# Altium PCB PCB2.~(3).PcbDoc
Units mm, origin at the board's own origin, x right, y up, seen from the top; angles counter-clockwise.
Board outline 101.6 x 109.09 mm, 2 copper layers (Top Layer, Bottom Layer); 25 components, 22 nets, 119 pads, 0 vias.
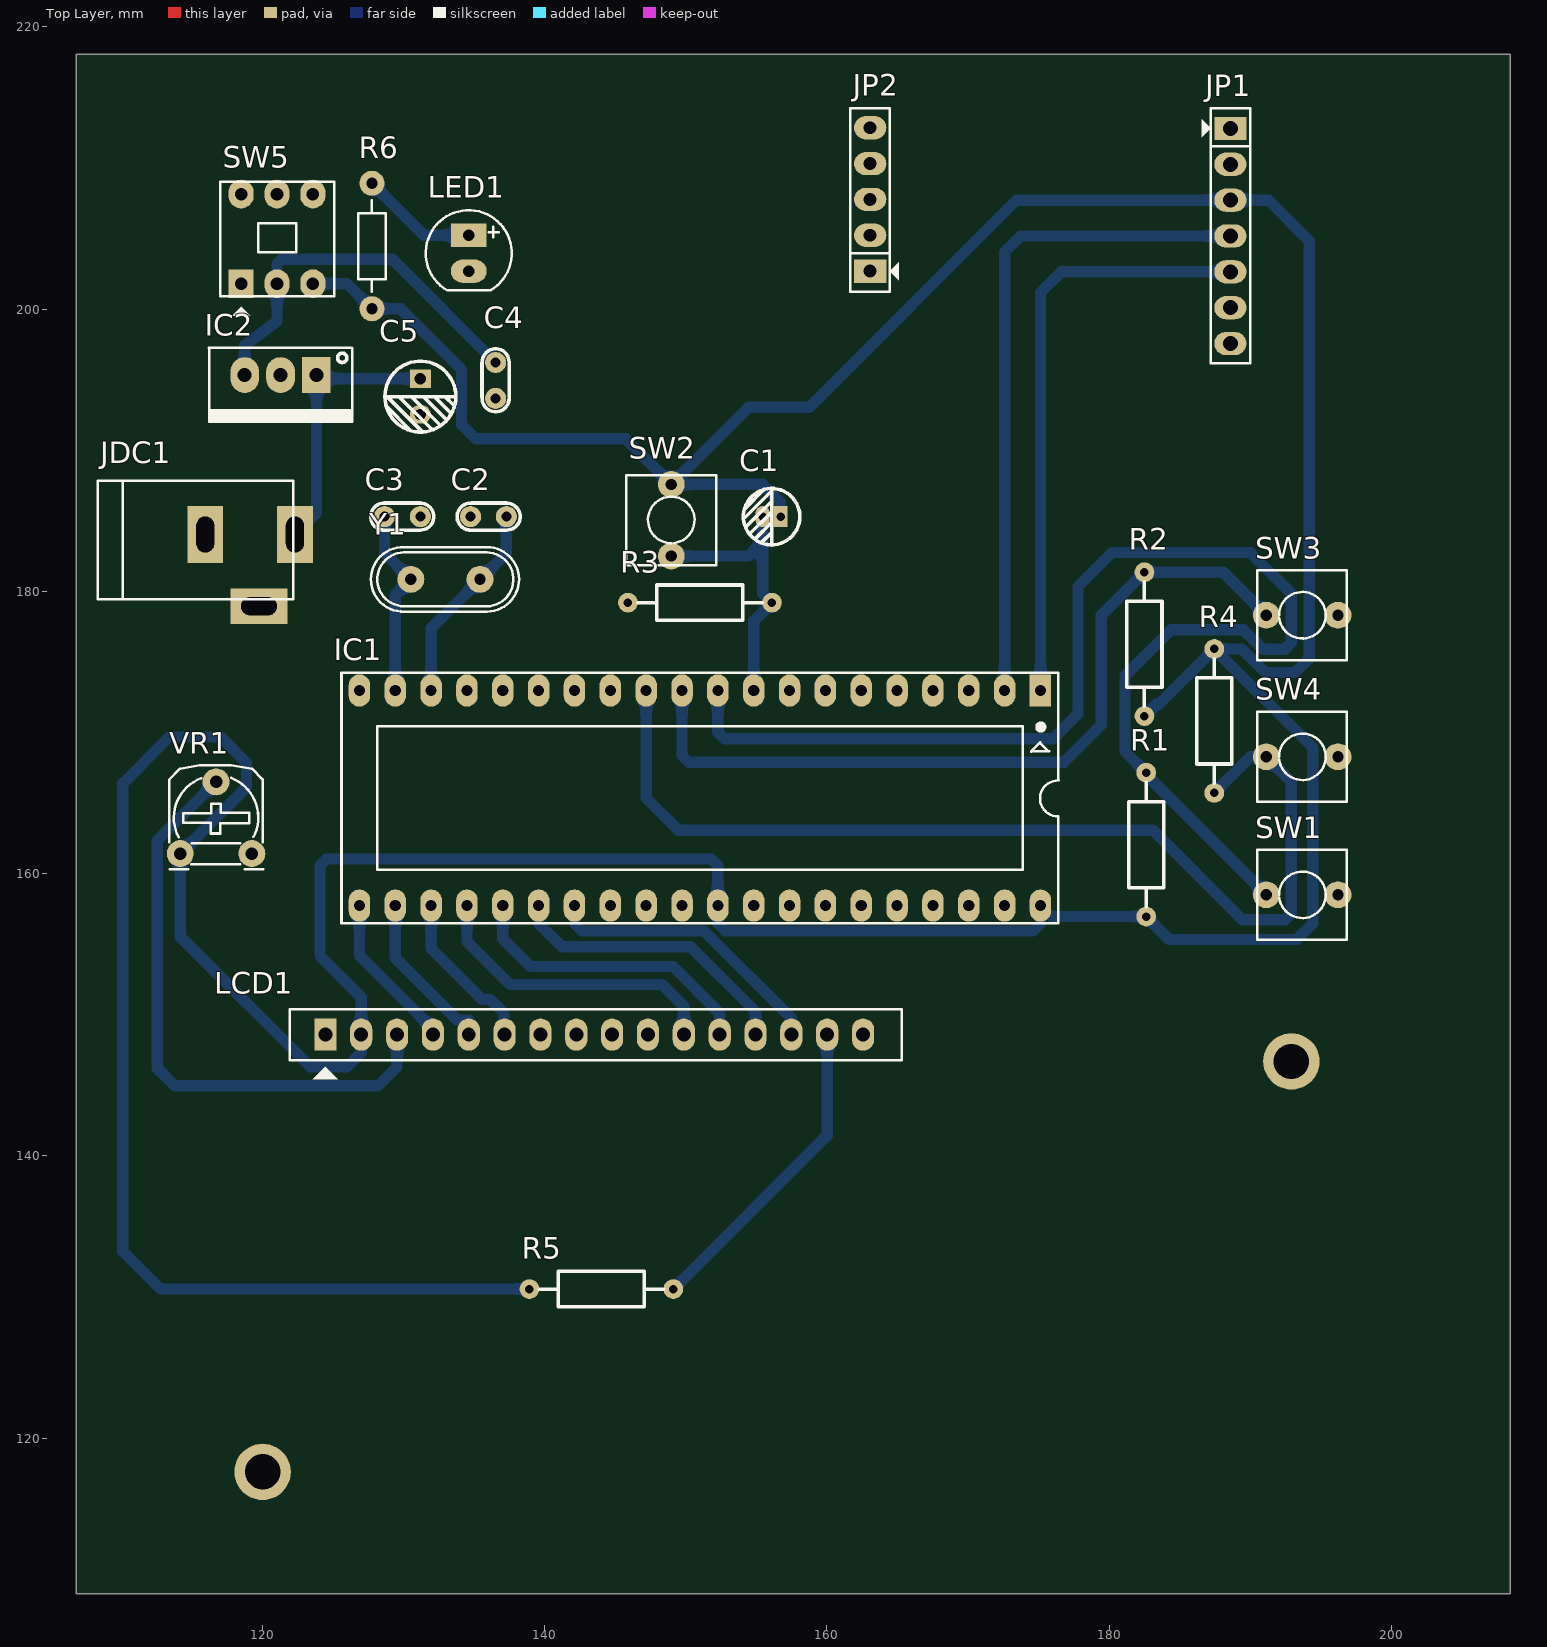
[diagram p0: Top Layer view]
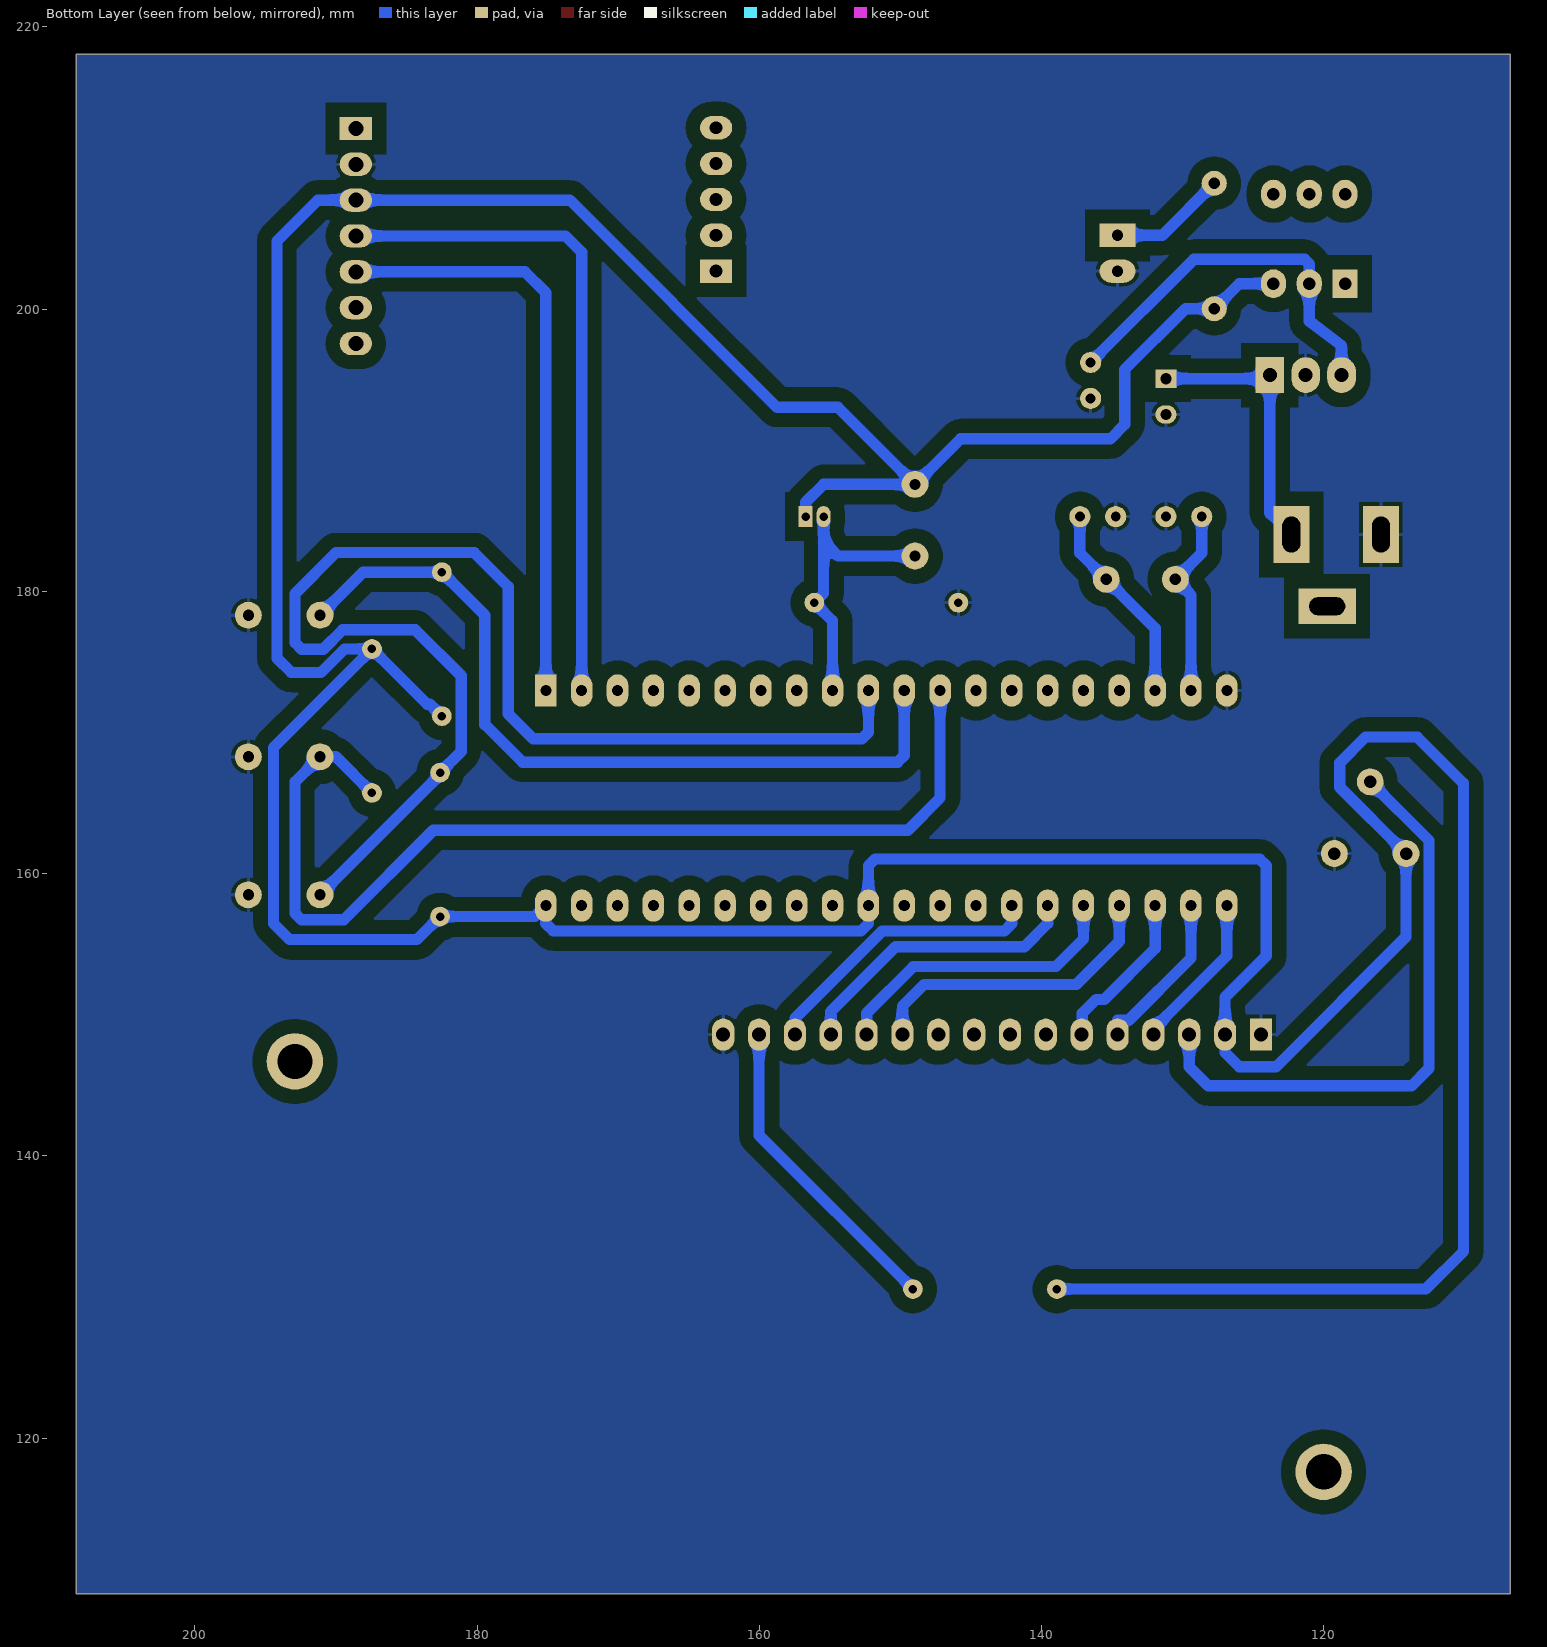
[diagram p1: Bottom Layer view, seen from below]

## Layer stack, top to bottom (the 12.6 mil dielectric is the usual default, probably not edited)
Top Solder: solder mask 0.0102, Solder Resist, Dk 3.5
Top Layer: signal copper 0.0356
Dielectric 1: dielectric 0.32, FR-4, Dk 4.8
Bottom Layer: signal copper 0.0356
Bottom Solder: solder mask 0.0102, Solder Resist, Dk 3.5

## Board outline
106.807,218.059 106.807,108.966 208.407,108.966 208.407,218.059

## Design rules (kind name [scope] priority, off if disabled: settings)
Clearance [All] p1: gap=0.2 ignorepadtopadclearanceinfootprint=FALSE
PolygonConnect [All] p1: connectstyle=Relief reliefconductorwidth=0.254 reliefentries=4 polygonreliefangle="90 Angle" airgapwidth=0.254
RoutingLayers [All] p1: top layer_v5=FALSE bottom layer_v5=TRUE
RoutingVias [All] p1: holewidth=0.711 width=1.27 viastyle="Through Hole" minholewidth=0.711 minwidth=1.27 maxholewidth=0.711 maxwidth=1.27
SolderMaskExpansion [All] p1: expansion=0.102 istentingtop=FALSE
Width [All] p1: maxlimit=0.8 minlimit=0.254 preferedwidth=0.8
29 further rules are at their usual default settings.

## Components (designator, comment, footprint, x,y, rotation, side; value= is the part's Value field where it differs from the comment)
C1 "10uF" "tu hoa 4mm" 156.083,185.293 r180 top
C2 "30pF" "tu gom" 136.017,185.293 r180 top
C3 "30pF" "tu gom" 129.921,185.293 r0 top
C4 "104" "tu gom" 136.525,194.945 r270 top
C5 "22uF" "tu hoa 5mm" 131.191,193.802 r270 top
IC1 "AT89S52" DIP40/W0.6 175.133,172.974 r180 top
IC2 "LM7805" QTO-220 123.825,195.326 r180 top
JDC1 "Jack DC" DC-IN 119.126,181.483 r0 top value="Jac DC"
JP1 "JP7 PIN" JP7_1 188.595,212.801 r270 top value=JP7
JP2 "JP5 PIN" JP5_1 163.068,202.692 r90 top value=JP5
LCD1 "LCD1602 XL" "LCD1602 with Jump" 124.46,148.59 r0 top
LED1 "LED" LED-5-RED 134.62,205.232 r270 top value="LED 3 ly Single Colour"
R1 "10K" "tro vach 1/4w" 182.626,162.052 r90 top
R2 "10K" "tro vach 1/4w" 182.499,176.256 r90 top
R3 "10k" "tro vach 1/4w" 151.003,179.197 r0 top
R4 "10K" "tro vach 1/4w" 187.452,170.815 r270 top
R5 "220R" "tro vach 1/4w" 144.018,130.556 r0 top
R6 "1k" R1/4W 127.762,208.915 r270 top value="R1/4W - 1K"
SW1 "SW" SW2 196.215,158.496 r180 top value="SW chip 2 pin"
SW2 "SW" SW2 148.971,187.579 r270 top value="SW chip 2 pin"
SW3 "SW" SW2 196.215,178.308 r180 top value="SW chip 2 pin"
SW4 "SW" SW2 196.215,168.275 r180 top value="SW chip 2 pin"
SW5 "SW6A" SW6 118.491,201.803 r90 top value=SW6
VR1 "1K" "Bien Tro Tam Giac Dung" 114.173,161.417 r0 top
Y1 "11Mhz" "Thach Anh 2 chan cam" 132.969,180.848 r0 top value=4Mhz

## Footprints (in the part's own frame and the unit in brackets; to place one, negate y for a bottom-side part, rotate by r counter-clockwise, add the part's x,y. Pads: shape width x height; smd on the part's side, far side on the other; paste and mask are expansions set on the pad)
"Bien Tro Tam Giac Dung" [mil] "RM065"
  round 75 hole 35: 1(0,0) 2(100,200) 3(200,0)
  silkscreen extent -31,-44 231,246, body extent -28,-50 228,228, height 279
DC-IN [mil] "Jac DC input"
  rect 100x160 hole 50 slot 100 at 90 deg: 1(125,100) 2(-125,100)
  rect 160x100 hole 50 slot 100 at 0 deg: 3(25,-100)
  silkscreen extent -425,-80 120,250, body extent -410,-105 134,269, height 434
DIP40/W0.6 [mil] "40 PIN, W 600mil, Pin to pin 100mil"
  rect 60x90 hole 31: 1(0,0)
  oval 60x90 hole 31: 2(100,0) 3(200,0) 4(300,0) 5(400,0) 6(500,0) 7(600,0) 8(700,0) 9(800,0) 10(900,0) 11(1000,0) 12(1100,0) 13(1200,0) 14(1300,0) 15(1400,0) 16(1500,0) 17(1600,0) 18(1700,0) 19(1800,0) 20(1900,0) 21(1900,600) 22(1800,600) 23(1700,600) 24(1600,600) 25(1500,600) 26(1400,600) 27(1300,600) 28(1200,600) 29(1100,600) 30(1000,600) 31(900,600) 32(800,600) 33(700,600) 34(600,600) 35(500,600) 36(400,600) 37(300,600) 38(200,600) 39(100,600) 40(0,600)
  silkscreen extent -50,-50 1950,650, body extent -82,-10 1982,600, height 224
JP5_1 [mil] "JP5"
  rect 65x90 hole 36: 1(0,0)
  oval 65x90 hole 36: 2(100,0) 3(200,0) 4(300,0) 5(400,0)
  silkscreen extent -57,-80 455,55, body extent -55,-48 455,50, height 366
JP7_1 [mil] "JP7"
  rect 65x90 hole 42: 1(0,0)
  oval 65x90 hole 42: 2(100,0) 3(200,0) 4(300,0) 5(400,0) 6(500,0) 7(600,0)
  silkscreen extent -57,-80 655,55, body extent -53,-47 657,51, height 366
"LCD1602 with Jump" [mil] "LCD dipslay 16x2, 16 pin"
  rect 62x90 hole 39: 1(0,0)
  oval 62x90 hole 39: 2(100,0) 3(200,0) 4(300,0) 5(400,0) 6(500,0) 7(600,0) 8(700,0) 9(800,0) 10(900,0) 11(1000,0) 12(1100,0) 13(1200,0) 14(1300,0) 15(1400,0) 16(1500,0)
  silkscreen extent -100,-125 1608,70, body extent -320,-1353 2850,84, height 764
LED-5-RED [mil] "LED 2 PIN, 5 ly , Only colour,pin to pin 100mil"
  rect 65x100 hole 32: 1(0,0)
  oval 65x100 hole 32: 2(100,0)
  silkscreen extent -70,-120 154,120, body extent -65,-119 149,118, height 339
QTO-220 [mil] "TO-220 - 1-2-3"
  rect 80x100 hole 39: 1(0,0)
  oval 80x100 hole 39: 2(100,0) 3(200,0)
  silkscreen extent -100,-76 300,130, body extent -119,-64 322,121, height 755
R1/4W [mil] "R 1/4W, 2 Pin, 350mil"
  round 70 hole 31: 1(0,0) 2(350,0)
  silkscreen extent 48,-38 302,38, body extent -40,-47 386,47, height 111
SW2 [mil] "SW button 2pin, 250x 250 mil"
  round 75 hole 31: 1(0,0) 2(200,0)
  silkscreen extent -25,-125 225,125
SW6 [mil] "SW DTDP - 6Pin 260x300x300 mil"
  rect 80x70 hole 35: 1(0,0)
  oval 80x70 hole 35: 2(0,-100) 3(0,-200) 4(250,-200) 5(250,-100) 6(250,0)
  silkscreen extent -90,-260 285,58, body extent -33,-259 281,55, height 532
"Thach Anh 2 chan cam" [mm]
  round 1.905 hole 0.8: 1(-2.45,0) 2(2.45,0)
  silkscreen extent -5.28,-2.29 5.21,2.29, body extent -5.68,-2.36 5.68,2.29, height 3.5
"tro vach 1/4w" [mm]
  round 1.4 hole 0.6: 1(-5.1,0) 2(5.1,0)
  silkscreen extent -4.39,-1.25 4.42,1.25, body extent -5.38,-1.2 5.38,1.2, height 2.41
"tu gom" [mm] "Tu gom mini"
  round 1.5 hole 0.7: 1(-1.27,0) 2(1.27,0)
  silkscreen extent -2.25,-0.97 2.22,0.97, body extent -2.92,-0.85 2.92,0.85, height 6.12
"tu hoa 4mm" [mm]
  rect 1x1.5 hole 0.6: 1(-0.635,0)
  oval 1x1.5 hole 0.6: 2(0.635,0)
  silkscreen extent -2,-2 2.01,2.01, body extent -2.47,-2.47 2.58,2.58, height 14.81
"tu hoa 5mm" [mm]
  rect 1.3x1.5 hole 0.8: 1(-1.27,0)
  oval 1.3x1.5 hole 0.8: 2(1.27,0)
  silkscreen extent -2.51,-2.51 2.51,2.51, body extent -3.12,-3.18 3.23,3.18, height 14.55

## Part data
C1: library part "Tu Hoa 10uF 25V 4x7", "Cắm"
C2 C3: library part "Tu gom 30pF 50V", "Cắm"
C4: library part "Tu gom 104 50V", "Cắm"
C5: library part "Tu Hoa 22uF 50V 5x10", "Cắm"
IC1: "AT89S52, 8k Byte Flash Memory , 40 Pin"
IC2: library part LM78xx, "On ap +, from + 5 to + 24VDC"
JDC1: library part DCIN, "Jac DC input"
JP1: library part JP7
JP2: library part JP5
LCD1: "LCD 1602 Xanh Lá"
LED1: "LED Single colour Green and Red"
R1 R2 R4 R5: library part "Tro Vach 1/4W 5% 220R", "Cắm"
R3: library part "Tro Vach 1/4W 5% 10k", "Căm"
R6: library part R1/4W, "Resistor 1/4W"
SW1 SW2 SW3 SW4: library part SW2, "Switch button 2 pin"
SW5: "SW-DTDP - 6 Pin"
VR1: library part "Bien tro tam giac 1K Dung", "Cắm"
Y1: library part "Thach Anh 2 chan Cam", "Crystal For all Crystal 2pin."

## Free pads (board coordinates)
  round 4 hole 2.5: 8(120.015,117.602) 8(192.913,146.685)

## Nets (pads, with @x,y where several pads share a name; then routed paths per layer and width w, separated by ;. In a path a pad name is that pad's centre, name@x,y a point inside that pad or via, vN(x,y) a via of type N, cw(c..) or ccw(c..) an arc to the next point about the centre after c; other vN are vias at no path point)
D4: IC1.24 LCD1.11 | length 21.8
  Bottom Layer w0.8: IC1.24 134.493,155.194 137.541,152.146 148.336,152.146 149.86,150.622 LCD1.11
D5: IC1.25 LCD1.12 | length 21.4
  Bottom Layer w0.8: IC1.25 137.033,155.372 138.989,153.416 149.085,153.416 152.4,150.101 LCD1.12
D6: IC1.26 LCD1.13 | length 20.9
  Bottom Layer w0.8: IC1.26 139.573,156.464 141.224,154.813 150.343,154.813 154.94,150.216 LCD1.13
D7: IC1.27 LCD1.14 | length 20.6
  Bottom Layer w0.8: IC1.27 142.113,156.464 142.64,155.937 151.289,155.937 157.48,149.746 LCD1.14
DOWN: IC1.12 R4.2 SW4.2 | length 73.7
  Bottom Layer w0.8: IC1.12 147.193,165.354 149.479,163.068 183.109,163.068 189.459,156.718 192.444,156.718 192.913,157.187 192.913,166.497 SW4.2 190.012,168.275 R4.2
EN: IC1.23 LCD1.6 | length 11.6
  Bottom Layer w0.8: IC1.23 131.953,154.686 135.56,151.079 136.144,151.079 137.113,150.11 137.113,148.637 LCD1.6
GND: C2.2 C3.2 C4.2 C5.2 IC1.20 IC2.2 JDC1.2 JP1.2 LCD1.1 LCD1.16 LED1.2 R3.1 SW1.1 SW3.1 SW4.1 VR1.3
NetC2_1: C2.1 IC1.18 Y1.2 | length 14.5
  Bottom Layer w0.8: IC1.18 131.953,177.382 Y1.2 137.287,182.716 C2.1
NetC3_1: C3.1 IC1.19 Y1.1 | length 13.6
  Bottom Layer w0.8: C3.1 128.651,182.716 Y1.1 129.413,179.742 IC1.19
NetC4_1: C4.1 IC2.3 SW5.2 | length 27.7
  Bottom Layer w0.8: IC2.3 118.745,197.409 121.031,199.136 SW5.2 121.031,203.2 121.361,203.53 129.21,203.53 C4.1
NetC5_1: C5.1 IC2.1 JDC1.1 | length 19.3
  Bottom Layer w0.8: JDC1.1 123.825,185.547 IC2.1@123.825,195.072 ; IC2.1 IC2.1@123.825,195.072 ; C5.1 IC2.1@123.825,195.072
NetLCD1_15: LCD1.15 R5.2 | length 22.5
  Bottom Layer w0.8: R5.2 160.02,141.458 LCD1.15
NetLED1_1: LED1.1 R6.1 | length 8.4
  Bottom Layer w0.8: R6.1 131.445,205.232 LED1.1
RS: IC1.21 LCD1.4 | length 11.3
  Bottom Layer w0.8: IC1.21 126.873,154.184 132.08,148.977 LCD1.4
RST: C1.2 IC1.9 R3.2 SW2.2 | length 20
  Bottom Layer w0.8: SW2.2 154.432,182.499 155.448,183.515 ; IC1.9 154.813,177.907 R3.2 155.448,179.852 155.448,183.515 ; C1.2 155.448,183.515
RW: IC1.22 LCD1.5 | length 11.8
  Bottom Layer w0.8: IC1.22 129.413,154.013 133.82,149.606 134.62,149.606 LCD1.5
SCL: IC1.1 JP1.5 | length 42.3
  Bottom Layer w0.8: IC1.1 175.133,201.168 176.606,202.641 JP1.5
SDA: IC1.2 JP1.4 | length 47.5
  Bottom Layer w0.8: IC1.2 172.593,204.038 173.736,205.181 JP1.4
SET: IC1.10 R1.2 SW1.2 | length 92.8
  Bottom Layer w0.8: IC1.10 152.273,170.014 152.742,169.545 176.022,169.545 177.8,171.323 177.8,180.34 180.213,182.753 189.992,182.753 192.913,179.832 192.913,176.364 192.444,175.895 190.909,175.895 189.535,177.269 184.381,177.269 181.127,174.015 181.127,168.651 R1.2 182.626,167.005 SW1.2
UP: IC1.11 R2.2 SW3.2 | length 57.6
  Bottom Layer w0.8: IC1.11 149.733,168.363 150.202,167.894 176.79,167.894 179.451,170.555 179.451,178.308 R2.2 188.087,181.356 SW3.2
VCC: C1.1 IC1.31 IC1.40 JP1.3 LCD1.2 R1.1 R2.1 R4.1 R5.1 R6.2 SW2.1 SW5.3 VR1.1 | length 362.1
  Bottom Layer w0.8: SW5.3 125.984,201.803 R6.2 129.794,200.025 134.112,195.707 134.112,191.821 135.128,190.805 145.745,190.805 SW2.1 ; R5.1 112.776,130.556 110.109,133.223 110.109,166.395 113.386,169.672 117.043,169.672 118.872,167.843 118.872,166.116 VR1.1 114.173,155.524 123.393,146.304 125.984,146.304 127,147.32 LCD1.2 127,151.232 124.079,154.153 124.079,160.567 124.548,161.036 151.804,161.036 152.273,160.567 152.273,156.464 152.806,155.931 174.6,155.931 175.133,156.464 IC1.40 175.915,156.952 R1.1 184.257,155.321 193.294,155.321 194.437,156.464 194.437,168.93 R4.1 ; C1.1 156.718,186.309 155.448,187.579 SW2.1 ; R2.1 183.349,172.006 183.543,172.006 R4.1 ; SW2.1 154.432,193.04 158.75,193.04 173.431,207.721 JP1.3 191.287,207.721 194.183,204.826 194.183,175.26 193.167,174.244 191.069,174.244 189.398,175.915 R4.1
VEE: LCD1.3 VR1.2 | length 42.4
  Bottom Layer w0.8: VR1.2 112.547,162.331 112.547,146.202 113.792,144.958 128.194,144.958 129.54,146.304 LCD1.3
pads on no net: IC1.3 IC1.4 IC1.5 IC1.6 IC1.7 IC1.8 IC1.13 IC1.14 IC1.15 IC1.16 IC1.17 IC1.28 IC1.29 IC1.30 IC1.32 IC1.33 IC1.34 IC1.35 IC1.36 IC1.37 IC1.38 IC1.39 JDC1.3 JP1.1 JP1.6 JP1.7 JP2.1 JP2.2 JP2.3 JP2.4 JP2.5 LCD1.7 LCD1.8 LCD1.9 LCD1.10 SW5.1 SW5.4 SW5.5 SW5.6

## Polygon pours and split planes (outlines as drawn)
GND on Bottom Layer "GND_L02_P000" (solid, pour order 0): 106.807,108.966 208.407,108.966 208.407,218.059 106.807,218.059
